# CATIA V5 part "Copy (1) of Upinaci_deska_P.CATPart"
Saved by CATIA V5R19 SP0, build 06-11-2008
Part number: Copy (1) of Upinaci_deska_P
Nomenclature: FM 50_75 75_20.5_2312
Source: Unknown
Description: PART-FM 50_75 75_20.5_2312-DESC
Bounding box of the stored display mesh (mm): x -37.5 to 37.5, y -37.5 to 37.5, z 0 to 20.5
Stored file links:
  C:\Users\jsmid\Desktop\DP_Smidak_Forma LEGO\Copy (1) of Upinaci_deska_P.CATPart
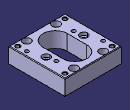
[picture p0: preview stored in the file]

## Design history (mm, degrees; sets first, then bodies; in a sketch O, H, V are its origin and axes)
Body1 "FM 50_75 75_20.5_2312" (main body)
  Solid1: solid without history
